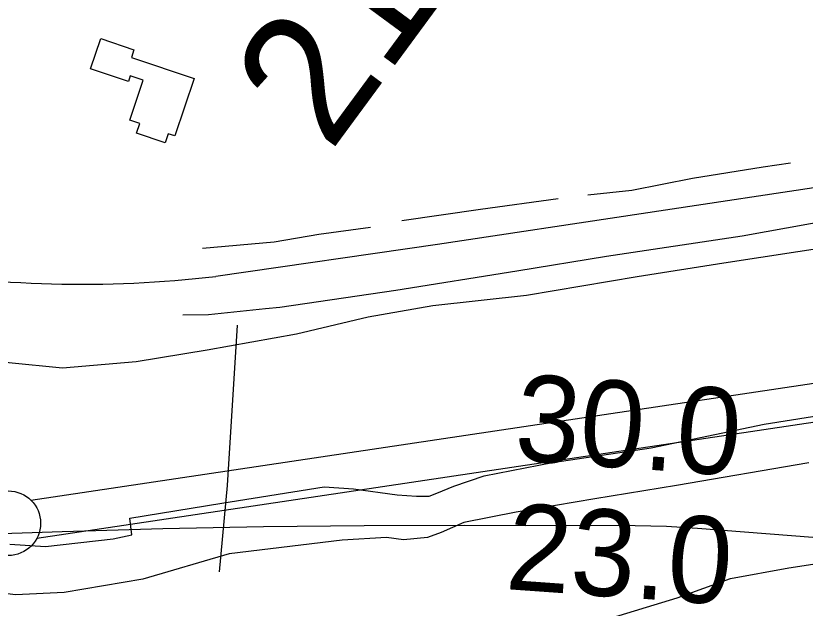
# Model space of a CAD drawing. Extents: x 3355677 to 3393573, y 612928 to 638357.
# Drawn here: x 3366586 to 3367196, y 624662 to 625120 of the extents above; entities that cross this region are included whole.
import ezdxf

# ---------------------------------------------------------------- set-up
doc = ezdxf.new("R2010")
doc.units = 0
for name, color, linetype in [('V-BLDG-OTLN', 7, 'Continuous'), ('V-FLOD-BASE', 7, 'Continuous'), ('V-LEVE-TOET', 7, 'Continuous'), ('V-RIVR-RANG', 7, 'Continuous'), ('V-ROAD-CNTR', 7, 'Continuous'), ('V-SURV-IDEN', 7, 'Continuous'), ('V-SURV-LINE', 7, 'Continuous'), ('V-TOPO-MAJR', 7, 'Continuous'), ('V-TOPO-SHOR', 7, 'Continuous'), ('V-UTIL-LINE', 7, 'Continuous'), ('V-WETL-SWMP', 7, 'Continuous')]:
    doc.layers.add(name, color=color, linetype=linetype)

msp = doc.modelspace()

# ---------------------------------------------------------------- linework, layer by layer
at = {"layer": 'V-BLDG-OTLN'}
msp.add_lwpolyline([(3366675.28, 625087.74), (3366723.78, 625071.55), (3366708.88, 625026.98), (3366703.79, 625028.69), (3366701.42, 625021.61), (3366679.29, 625029.03), (3366681.82, 625036.56), (3366674.09, 625039.16), (3366684.4, 625070.07), (3366674.39, 625073.42), (3366672.92, 625069.05), (3366643.61, 625078.92), (3366651.5, 625102.36), (3366677.17, 625093.71)], close=True, dxfattribs=at)
at = {"layer": 'V-FLOD-BASE'}
msp.add_lwpolyline([(3366581.13, 624711.2), (3366608.95, 624709.33), (3366661.07, 624715.31), (3366675.62, 624718.41), (3366674.13, 624731.33), (3366745.25, 624742.79), (3366824.46, 624755.39), (3366847.05, 624753.97), (3366880.9, 624749.22), (3366895.83, 624748.28), (3366905.51, 624748.19), (3366911.58, 624750.56), (3366924.55, 624756.09), (3366948.03, 624763.94), (3367000.99, 624774.36), (3367077.36, 624785.77), (3367164.69, 624803.94), (3367234.6, 624815)], dxfattribs=at)
at = {"layer": 'V-LEVE-TOET'}
for points in [[(3366001.56, 625011.88), (3366083.66, 624988.12), (3366159.75, 624968.06), (3366216.11, 624953.42), (3366301.06, 624931.67), (3366362.25, 624915.37), (3366420.6, 624897.48), (3366491.44, 624877.47), (3366515.99, 624869.58), (3366552.21, 624859.56), (3366580.39, 624851.64), (3366621.92, 624847.62), (3366678.86, 624852.35), (3366733.83, 624861.54), (3366802.95, 624873.82), (3366858.35, 624887.04), (3366908.47, 624895.86), (3366980.78, 624903.68), (3367066.46, 624918.23), (3367133.55, 624928.92), (3367247.91, 624946.44)], [(3367199.12, 624774.16), (3367096.87, 624756.53), (3367033.82, 624746.21), (3366972.79, 624735.87), (3366932.36, 624727.77), (3366914.94, 624720.26), (3366904.41, 624716.32), (3366885.83, 624714.47), (3366872.53, 624716.21), (3366838.21, 624714.1), (3366750.95, 624703.6), (3366684.19, 624684.03), (3366623.16, 624673.69), (3366585.61, 624672.01), (3366526.76, 624679.41), (3366446.27, 624702.74), (3366356.9, 624726.56), (3366278.01, 624749.07), (3366199.5, 624768.75), (3366122.19, 624788.42), (3366028.42, 624815.91), (3365945.08, 624837.66)]]:
    msp.add_lwpolyline(points, dxfattribs=at)
at = {"layer": 'V-ROAD-CNTR'}
msp.add_lwpolyline([(3367362.84, 625008.07), (3367227.14, 624990.44), (3366912.07, 624943.04), (3366740.57, 624918.27)], dxfattribs=at)
msp.add_arc((3366636.94, 625805.78), 893.54, 260.34175, 276.66015, dxfattribs=at)
at = {"layer": 'V-SURV-LINE'}
for points in [[(3366597.59, 624745.12), (3367399.88, 624865.02)], [(3367404.3, 624835.35), (3366602.01, 624715.45)]]:
    msp.add_lwpolyline(points, dxfattribs=at)
msp.add_circle((3366580.04, 624727.33), 25, dxfattribs=at)
at = {"layer": 'V-TOPO-MAJR'}
msp.add_lwpolyline([(3367869.83, 624664.26), (3367113.06, 624723.33), (3367101.06, 624724.13), (3367089.06, 624724.75), (3367077.05, 624725.1), (3367065.03, 624725.27), (3366933.27, 624725.61), (3366855.37, 624725.39), (3366777.49, 624724.59), (3366699.61, 624722.95), (3366621.75, 624720.73), (3366411.78, 624713.61), (3366388.3, 624712.96), (3366364.81, 624712.51), (3366341.32, 624712.36), (3366317.83, 624712.41), (3366203.62, 624713.37), (3366123.03, 624714.28), (3366042.44, 624715.5), (3365961.86, 624717.2)], dxfattribs=at)
at = {"layer": 'V-TOPO-SHOR'}
for points in [[(3367028.25, 624981.43), (3367062.4, 624985.01), (3367109.29, 624994.27), (3367163.85, 625003.05), (3367184.98, 625006.15)], [(3368046.78, 624942.03), (3367970.23, 624949.35), (3367864.27, 624957.77), (3367724.37, 624967.33), (3367608.91, 624977.5), (3367495.05, 624981.43), (3367393.57, 624980.7), (3367330.15, 624975.48), (3367234.8, 624965.17), (3367147.68, 624949.4), (3367042.75, 624933.79), (3366973.48, 624922.41), (3366879.74, 624907.52), (3366790.16, 624894.26), (3366778.96, 624893.12), (3366735.02, 624888.55), (3366715.14, 624888.32)], [(3366884.43, 624961.52), (3366945.23, 624970.34), (3367005.48, 624978.61)], [(3366730.37, 624940.19), (3366785.6, 624945.16), (3366820.36, 624950.9), (3366860.13, 624956.44)]]:
    msp.add_lwpolyline(points, dxfattribs=at)
at = {"layer": 'V-UTIL-LINE'}
msp.add_lwpolyline([(3366756.97, 624880.62), (3366749.39, 624756.59), (3366743.03, 624689.67)], dxfattribs=at)
at = {"layer": 'V-WETL-SWMP'}
msp.add_lwpolyline([(3367187.48, 624644.46), (3367172.84, 624631.68), (3367172.49, 624592.94), (3367170.31, 624531.62), (3367146.68, 624506.01), (3367109.54, 624505.54), (3367052.14, 624493.96), (3367009.44, 624503.23), (3366957.15, 624521.46), (3366900.61, 624516.33), (3366886.13, 624522.11), (3366880.63, 624538.3), (3366901.17, 624578.47), (3366931.38, 624616.12), (3366974.31, 624633.49), (3367040.67, 624652.26), (3367097.32, 624669.49), (3367138.62, 624684.45), (3367183.89, 624692.92), (3367208.95, 624696.72), (3367229.92, 624695.73), (3367227.32, 624676.38), (3367212.63, 624657.95), (3367199.64, 624650)], close=True, dxfattribs=at)

# ---------------------------------------------------------------- texts
at = {"layer": 'V-RIVR-RANG'}
for s, p in [('30.0', (3366970.59, 624776.16)), ('23.0', (3366963.77, 624676.39))]:
    msp.add_text(s, height=67, rotation=355.94833, dxfattribs=at).set_placement(p)
at = {"layer": 'V-SURV-IDEN'}
msp.add_text('2119+67.4', height=100, rotation=53.6599, dxfattribs=at).set_placement((3366829.03, 625013.65))

doc.saveas('drawing.dxf')
